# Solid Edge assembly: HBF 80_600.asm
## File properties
Title: Zylinder
Author: ahadarics
Template: iso assembly.asm
Last saved by: ahadarics
Revision: 45
Application: Solid Edge
Username: ahadarics
Dokumentum tartalom típus: 1
Document Number: HBF 80/600
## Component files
Kit.par
Profilrohr 80_600.par
Kolbenstange_1_80_600.par
Mutter.par
Kolbenstange_2_80_600.par
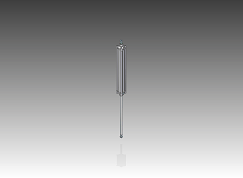
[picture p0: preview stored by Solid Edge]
